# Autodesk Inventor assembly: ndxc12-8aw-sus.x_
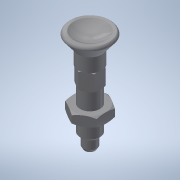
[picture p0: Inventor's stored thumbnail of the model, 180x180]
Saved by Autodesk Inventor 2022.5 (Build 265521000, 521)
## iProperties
Part Number: ndxc12-8aw-sus.x_
Material: 一般
Document SubType Name: Assembly
Designer: ImaoCorp
Sending System: SOLIDWORKS 2017-2017317
MC: AMD64
MC_MODEL: Intel64 Family 6 Model 60 Stepping 3, GenuineIntel
OS: Windows_NT
FRU: Parasolid Version 29.0, build 201,  4-17-2017
FORMAT: text
GUISE: transmit
KEY: ndxc12-8aw-sus
FILE: ndxc12-8aw-sus.x_t
DATE: Wed Sep 04 15:30:04 2019
Author: ImaoCorp
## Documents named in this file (3)
- X:\14_SW2022-Inv2022\00_全2023-1023新製品(TCC)まで\n\ndxc12-8aw-sus\NDXC12-8AW-SUS.iam
- X:\14_SW2022-Inv2022\00_全2023-1023新製品(TCC)まで\n\ndxc12-8aw-sus\ndxc12-8aw-sus_01.ipt
- X:\14_SW2022-Inv2022\00_全2023-1023新製品(TCC)まで\n\ndxc12-8aw-sus\ndxc12-8aw-sus_02.ipt
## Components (2 placed, 2 different names)
1. ndxc12-8aw-sus_01
2. ndxc12-8aw-sus_02
